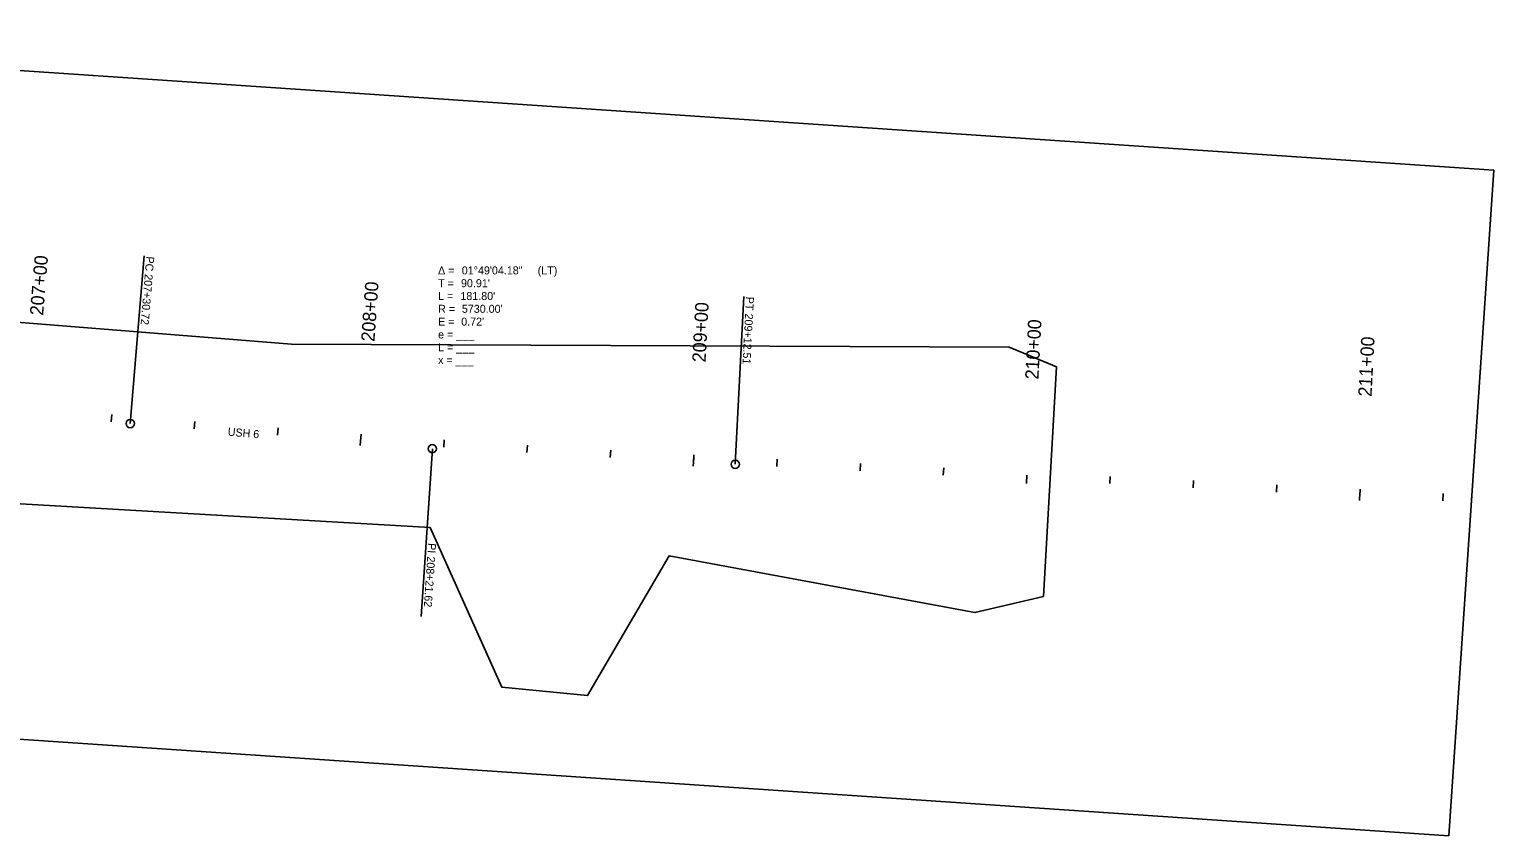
# Model space of a CAD drawing. Extents: x 20499876 to 20505320, y 7953544 to 7954108.
# Drawn here: x 20504399.3 to 20504838.4, y 7953543.8 to 7953785.6 of the extents above; entities that cross this region are included whole.
import ezdxf

# ---------------------------------------------------------------- set-up
doc = ezdxf.new("R2010")
doc.units = 0
for name, color, linetype in [('Alignment', 7, 'Continuous'), ('Curb', 7, 'Continuous'), ('Draft_0', 7, 'Continuous'), ('Draft_7', 7, 'Continuous'), ('Text', 7, 'Continuous'), ('UtilitiesBelowGround', 7, 'Continuous')]:
    doc.layers.add(name, color=color, linetype=linetype)

msp = doc.modelspace()

# ---------------------------------------------------------------- linework, layer by layer
at = {"layer": 'Alignment'}
msp.add_lwpolyline([(20504212.89, 7953785.63), (20504199.4, 7953586.08), (20504824.91, 7953543.82), (20504838.4, 7953743.37)], close=True, dxfattribs=at)
at = {"layer": 'Curb'}
for p, q in [((20504498.68, 7953662.08), (20504498.83, 7953664.26)), ((20504598.48, 7953655.84), (20504598.6, 7953658.03)), ((20504698.41, 7953651.9), (20504698.28, 7953649.46)), ((20504798.21, 7953645.53), (20504798.33, 7953647.71))]:
    msp.add_line(p, q, dxfattribs=at)
at = {"layer": 'Draft_7'}
for p, q in [((20504423.9, 7953667.9), (20504424.08, 7953670.08)), ((20504448.82, 7953665.85), (20504448.99, 7953668.03)), ((20504473.74, 7953663.91), (20504473.91, 7953666.09)), ((20504498.76, 7953663.3), (20504498.59, 7953660.86)), ((20504523.62, 7953660.36), (20504523.76, 7953662.54)), ((20504548.56, 7953658.75), (20504548.7, 7953660.93)), ((20504573.52, 7953657.24), (20504573.65, 7953659.42)), ((20504598.55, 7953657.07), (20504598.41, 7953654.62)), ((20504623.45, 7953654.54), (20504623.56, 7953656.72)), ((20504648.41, 7953653.26), (20504648.52, 7953655.44)), ((20504673.38, 7953651.97), (20504673.49, 7953654.15)), ((20504698.41, 7953651.9), (20504698.28, 7953649.46)), ((20504723.31, 7953649.39), (20504723.43, 7953651.58)), ((20504748.28, 7953648.11), (20504748.39, 7953650.29)), ((20504773.25, 7953646.82), (20504773.36, 7953649)), ((20504798.28, 7953646.76), (20504798.15, 7953644.31)), ((20504823.18, 7953644.25), (20504823.29, 7953646.43))]:
    msp.add_line(p, q, dxfattribs=at)
at = {"layer": 'Text'}
for p, q in [((20504429.6, 7953667.42), (20504433.79, 7953717.65)), ((20504433.79, 7953717.65), (20504433.79, 7953717.65)), ((20504610.98, 7953655.19), (20504613.57, 7953705.52)), ((20504613.57, 7953705.52), (20504613.57, 7953705.52)), ((20504520.19, 7953659.87), (20504516.8, 7953609.58)), ((20504516.8, 7953609.58), (20504516.8, 7953609.58))]:
    msp.add_line(p, q, dxfattribs=at)
for centre in [(20504429.6, 7953667.42), (20504520.19, 7953659.87), (20504610.98, 7953655.19)]:
    msp.add_circle(centre, 1.25, dxfattribs=at)
at = {"layer": 'UtilitiesBelowGround'}
msp.add_lwpolyline([(20503829.09, 7953744.97), (20504079.02, 7953722.08), (20504247.03, 7953709.66), (20504477.95, 7953691.2), (20504693.1, 7953690.35), (20504707.3, 7953684.41), (20504703.39, 7953615.5), (20504682.83, 7953610.75), (20504591.14, 7953627.72), (20504566.72, 7953585.85), (20504541.05, 7953588.36), (20504519.52, 7953636.21), (20504351.61, 7953645.9), (20504212.21, 7953659.14), (20503994.1, 7953676.75), (20503832.88, 7953690.55)], dxfattribs=at)

# ---------------------------------------------------------------- texts
at = {"layer": 'Curb'}
msp.add_text('210+00', height=4.008, rotation=87.0487, dxfattribs=at).set_placement((20504701.89, 7953680.54))
at = {"layer": 'Draft_0'}
msp.add_text('USH 6', height=2.4, rotation=355, dxfattribs=at).set_placement((20504458.76, 7953663.8))
at = {"layer": 'Draft_7'}
for s, rotation, p in [('207+00', 85.2308, (20504403.48, 7953699.71)), ('208+00', 85.9236, (20504502.81, 7953691.86)), ('209+00', 86.9235, (20504602.09, 7953685.69)), ('210+00', 87.0487, (20504701.89, 7953680.54)), ('211+00', 87.0487, (20504801.76, 7953675.39))]:
    msp.add_text(s, height=4.008, rotation=rotation, dxfattribs=at).set_placement(p)
at = {"layer": 'Text'}
for s, rotation, p in [('PC', 265.2308, (20504434.43, 7953717.6)), ('207+30.72', 265.2308, (20504433.99, 7953712.28)), ('PT', 267.0487, (20504614.22, 7953705.49)), ('209+12.51', 267.0487, (20504613.96, 7953700.45)), ('PI ', 266.1397, (20504518.93, 7953631.63)), ('208+21.62', 266.1397, (20504518.66, 7953627.64))]:
    msp.add_text(s, height=2.4, rotation=rotation, dxfattribs=at).set_placement(p)
for s, p in [('Δ = ', (20504521.9, 7953712.13)), ('01°49\'04.18"', (20504529.01, 7953712.13)), (' (LT)', (20504550.88, 7953712.13)), ('T = ', (20504521.9, 7953708.29)), ("90.91'", (20504528.77, 7953708.29)), ('L = ', (20504521.9, 7953704.45)), ("181.80'", (20504528.59, 7953704.45)), ('R = ', (20504521.9, 7953700.61)), ("5730.00'", (20504529.04, 7953700.61)), ('E = ', (20504521.9, 7953696.77)), ("0.72'", (20504528.84, 7953696.77)), ('e = ___ ', (20504521.9, 7953692.93)), ('L = ___', (20504521.9, 7953689.09)), ('x = ___', (20504521.9, 7953685.25))]:
    msp.add_text(s, height=2.4, dxfattribs=at).set_placement(p)

doc.saveas('drawing.dxf')
